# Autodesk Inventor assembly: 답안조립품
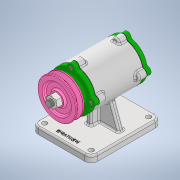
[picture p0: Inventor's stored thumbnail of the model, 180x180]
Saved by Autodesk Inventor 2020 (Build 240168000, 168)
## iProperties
Created: 2022-11
Part Number: 답안조립품
Document SubType Name: Assembly
Designer: owner
Author: owner
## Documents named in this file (12)
- C:\Users\owner\Desktop\721108V1003\답안조립품.iam
- C:\Users\owner\Desktop\721108V1003\본체.ipt
- C:\Users\owner\Desktop\721108V1003\Ű 4 x 4.ipt
- C:\Users\owner\Desktop\721108V1003\V-벨트풀리.ipt
- C:\Users\owner\Desktop\721108V1003\개스킷.ipt
- C:\Users\owner\Desktop\721108V1003\너트 M12 x 1.25.ipt
- C:\Users\owner\Desktop\721108V1003\뒤커버.ipt
- C:\Users\owner\Desktop\721108V1003\베어링 6204.ipt
- C:\Users\owner\Desktop\721108V1003\볼트 M4 x 12.ipt
- C:\Users\owner\Desktop\721108V1003\앞커버.ipt
- C:\Users\owner\Desktop\721108V1003\오일 실.ipt
- C:\Users\owner\Desktop\721108V1003\축.ipt
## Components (8 placed, 6 different names)
1. KS B 1311 (I) 4 x 4 x 12:1
2. V-벨트풀리:1 — 각도:1
3. 개스킷:1
4. KS B 1012 클래스 1 일반 - 미터 M12x1.25:1 — 각도:1
5. KS B 2023 6204 - 20 x 47 x 14:1
6. KS B 2804 D D - 20 32 8:1
7. KS B 2023 6204 - 20 x 47 x 14:2
8. 개스킷:2
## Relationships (1: Angle 1)
- 각도:1 [Angle]: V-벨트풀리:1 ↔ KS B 1012 클래스 1 일반 - 미터 M12x1.25:1
